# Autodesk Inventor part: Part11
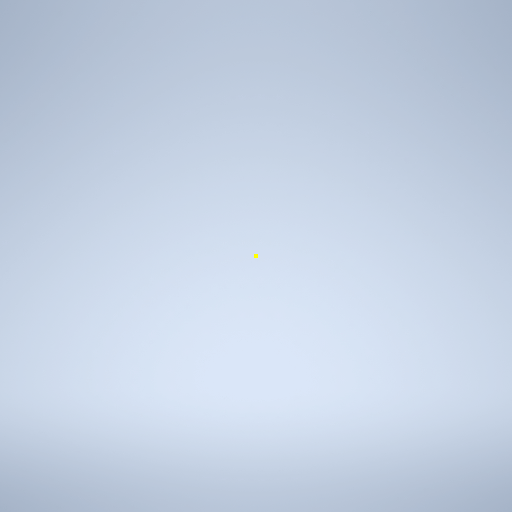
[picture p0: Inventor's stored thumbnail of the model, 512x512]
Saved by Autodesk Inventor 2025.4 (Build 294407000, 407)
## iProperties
Created: 2026-04
Part Number: Part11
Material: Generic
Document SubType Name: Modeling
Designer: PC
Density: 1 g/cm^3
Appearance: Default
Author: PC
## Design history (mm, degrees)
sketch "Sketch1"
  geometry: 1 further point
  constraints: 1 other
